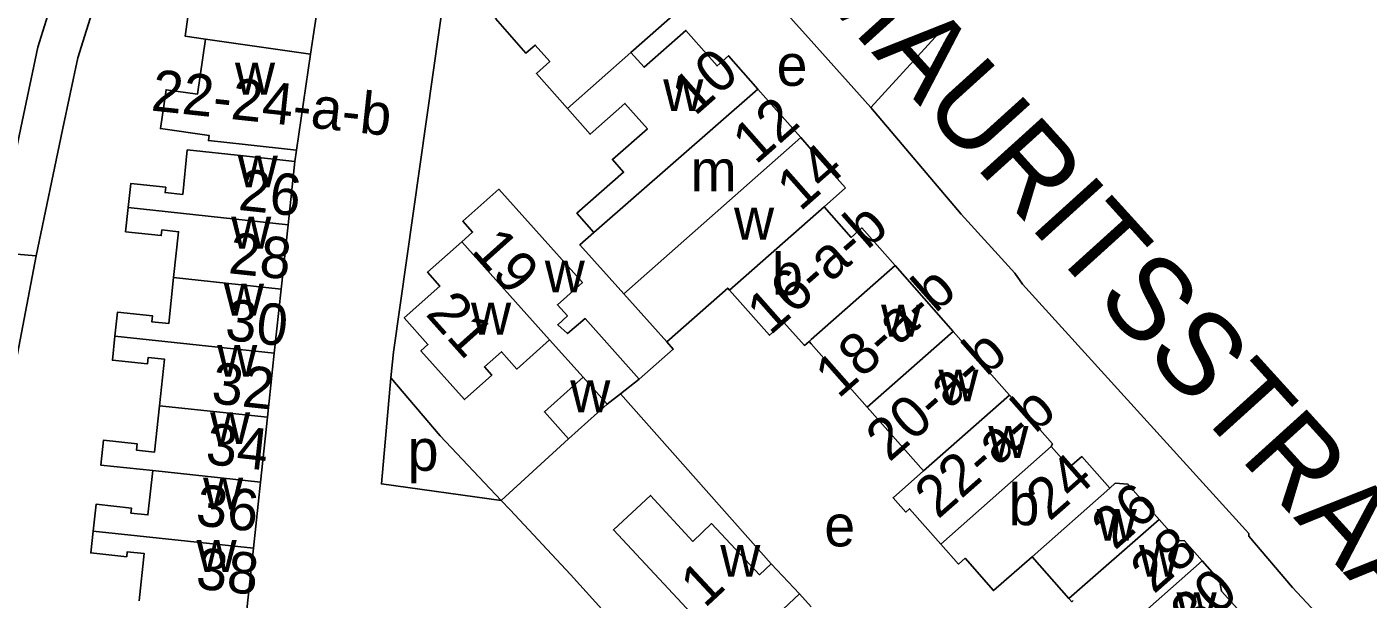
# Model space of a CAD drawing. Extents: x 159261 to 160849, y 382514 to 384534.
# Drawn here: x 160624.3 to 160753.7, y 383032.4 to 383087.7 of the extents above; entities that cross this region are included whole.
import ezdxf

# ---------------------------------------------------------------- set-up
doc = ezdxf.new("R2010")
doc.units = 0
for name, color, linetype in [('BLT_Basislijn', 7, 'Continuous'), ('BLT_Bebouwing', 7, 'Continuous'), ('BLT_Centroide', 7, 'Continuous'), ('BLT_Huisnummer', 7, 'Continuous'), ('BLT_Huisnummer_ tussenligend', 7, 'Continuous'), ('BLT_Huisnummer_reeks', 7, 'Continuous'), ('BLT_Onderverdeling_panden', 7, 'Continuous'), ('BLT_Straatnaam_hoofdweg', 7, 'Continuous'), ('BLT_Vlakafsluiter', 7, 'Continuous')]:
    doc.layers.add(name, color=color, linetype=linetype)

msp = doc.modelspace()

# ---------------------------------------------------------------- linework, layer by layer
at = {"layer": 'BLT_Basislijn'}
for p, q in [((160650.36, 383075.76), (160650.2, 383074.67)), ((160621.23, 383065.87), (160625.25, 383065.55)), ((160696.14, 383035.81), (160681.61, 383052.23)), ((160676.59, 383047.88), (160670.1, 383041.92))]:
    msp.add_line(p, q, dxfattribs=at)
for points in [[(160682.18, 383106.36), (160683.55, 383105.24), (160684.96, 383103.12), (160700, 383086.31)], [(160621.23, 383065.87), (160623.87, 383078.53), (160625.39, 383085.68), (160627.98, 383093.98), (160629.41, 383098.07)], [(160625.25, 383065.55), (160627.78, 383077.71), (160629.27, 383084.67), (160631.78, 383092.72), (160633.52, 383097.7)], [(160664.78, 383092.12), (160659.72, 383056.26), (160659.44, 383053.76)], [(160700, 383086.31), (160705.76, 383079.87)], [(160705.76, 383079.87), (160714.48, 383069.58), (160719.65, 383063.88), (160720.38, 383062.82), (160742.22, 383038.75), (160742.22, 383038.49), (160746.42, 383033.51), (160772.56, 383005.52)], [(160618.36, 383042.52), (160620.8, 383042.42), (160625.25, 383065.55)], [(160686.09, 383057.24), (160686.69, 383056.53), (160683.41, 383053.65)], [(160659.44, 383053.76), (160658.55, 383043.53), (160670.1, 383041.92)], [(160659.44, 383053.76), (160664.22, 383048.17), (160670.1, 383041.92)], [(160700, 383009.05), (160676.77, 383034.77), (160670.95, 383041.01), (160670.1, 383041.92)]]:
    msp.add_lwpolyline(points, dxfattribs=at)
at = {"layer": 'BLT_Bebouwing'}
for p, q in [((160652.55, 383090.74), (160651.71, 383085.03)), ((160650.36, 383075.76), (160651.71, 383085.03)), ((160699, 383076.96), (160694.87, 383081.65)), ((160700, 383075.83), (160699, 383076.96)), ((160703.3, 383072.1), (160700, 383075.83)), ((160649.55, 383068.55), (160650.2, 383074.67)), ((160701.25, 383070.29), (160703.3, 383072.1)), ((160648.88, 383062.33), (160649.55, 383068.55)), ((160648.21, 383056.14), (160648.88, 383062.33)), ((160686.09, 383057.24), (160681.92, 383061.88)), ((160678.01, 383053.83), (160674.77, 383057.44)), ((160700, 383057.06), (160699.8, 383057.29)), ((160647.55, 383049.96), (160648.21, 383056.14)), ((160683.41, 383053.65), (160681.61, 383052.23)), ((160646.88, 383043.7), (160647.55, 383049.96)), ((160646.2, 383037.31), (160646.88, 383043.7)), ((160645.53, 383031.12), (160646.2, 383037.31)), ((160696.14, 383035.81), (160698.86, 383032.9)), ((160698.86, 383032.9), (160700, 383031.67))]:
    msp.add_line(p, q, dxfattribs=at)
for points in [[(160676.48, 383079.78), (160673.49, 383083.16), (160674.78, 383084.3), (160673.38, 383085.89), (160672.49, 383085.11), (160669.54, 383088.46), (160680.54, 383098.16), (160683.77, 383094.51), (160682.44, 383093.34), (160683.46, 383092.18), (160683.79, 383092.47), (160683.95, 383092.28), (160685.48, 383092.18), (160686.92, 383090.55), (160686.87, 383088.95), (160682.61, 383085.19)], [(160642.06, 383092.27), (160641.72, 383089.97), (160640.1, 383090.21), (160639.6, 383086.77), (160641.57, 383086.48)], [(160694.87, 383081.65), (160692.03, 383084.86), (160690.93, 383083.89), (160687.91, 383087.31), (160683.88, 383083.75), (160682.61, 383085.19)], [(160641.57, 383086.48), (160640.79, 383081.15), (160637.77, 383081.59), (160637.23, 383077.84), (160641.93, 383077.16), (160641.86, 383076.67), (160645.39, 383076.29), (160650.36, 383075.76)], [(160679.05, 383067.8), (160677.41, 383069.66), (160681.91, 383073.62), (160680.83, 383074.85), (160684.2, 383077.82), (160682.04, 383080.26), (160678.67, 383077.29), (160676.48, 383079.78)], [(160634.11, 383070.2), (160634.36, 383072.53), (160637.73, 383072.17), (160637.68, 383071.65), (160639.37, 383071.47), (160639.8, 383075.78)], [(160650.2, 383074.67), (160645.23, 383075.2), (160639.8, 383075.78)], [(160683.41, 383053.65), (160678.2, 383059.49), (160676.5, 383058.04), (160675.56, 383058.9), (160676.49, 383059.74), (160675.52, 383060.82), (160677.93, 383062.97), (160673.2, 383068.25), (160669.87, 383071.97), (160666.41, 383068.88), (160667.34, 383067.84), (160666.29, 383066.9)], [(160638.49, 383063.44), (160638.97, 383067.88), (160637.36, 383068.05), (160637.3, 383067.5), (160633.86, 383067.87), (160634.11, 383070.2)], [(160708.09, 383064.6), (160704.89, 383068.24), (160703.86, 383067.33), (160701.25, 383070.29)], [(160681.92, 383061.88), (160677.68, 383066.6), (160679.05, 383067.8)], [(160666.29, 383066.9), (160663, 383063.96), (160664.19, 383062.63), (160660.74, 383059.55), (160663.03, 383056.99), (160662.35, 383056.38), (160666.57, 383051.67), (160669.19, 383054.02), (160668.48, 383054.82), (160670.12, 383056.29), (160671.62, 383054.61), (160674.77, 383057.44)], [(160713.71, 383058.24), (160708.09, 383064.6)], [(160632.84, 383057.79), (160633.09, 383060.11), (160636.46, 383059.74), (160636.4, 383059.17), (160638.02, 383059), (160638.49, 383063.44)], [(160692.13, 383062.24), (160691.96, 383062.43), (160686.09, 383057.24)], [(160699.8, 383057.29), (160699.35, 383056.89), (160697.37, 383059.12), (160695.97, 383057.88), (160692.13, 383062.24)], [(160719.13, 383052.09), (160713.71, 383058.24)], [(160637.14, 383051.07), (160637.62, 383055.56), (160636.04, 383055.73), (160635.97, 383055.11), (160632.6, 383055.47), (160632.84, 383057.79)], [(160705.41, 383050.93), (160700, 383057.06)], [(160678.01, 383053.83), (160674.27, 383050.47), (160676.59, 383047.88)], [(160680.31, 383051.22), (160681.61, 383052.23)], [(160723.15, 383047.14), (160723.28, 383047.39), (160719.13, 383052.09)], [(160636.48, 383044.81), (160631.47, 383045.35), (160631.73, 383047.74), (160634.99, 383047.39), (160634.93, 383046.78), (160636.66, 383046.59), (160637.14, 383051.07)], [(160676.59, 383047.88), (160680.31, 383051.22)], [(160710.84, 383044.78), (160705.41, 383050.93)], [(160728.81, 383043.12), (160726.11, 383046.17), (160724.93, 383045.13), (160723.15, 383047.14)], [(160630.73, 383038.97), (160631.01, 383041.56), (160634.43, 383041.19), (160634.37, 383040.71), (160636.02, 383040.53), (160636.48, 383044.81)], [(160712.51, 383037.7), (160709.49, 383041.12), (160709.14, 383040.81), (160707.91, 383042.19), (160710.84, 383044.78)], [(160733.58, 383040.1), (160730.56, 383043.51), (160729.34, 383043.59), (160728.81, 383043.12)], [(160696.14, 383035.81), (160695.01, 383034.75), (160690.4, 383039.69), (160688.57, 383037.98), (160684.49, 383042.41), (160680.92, 383039.09), (160689.73, 383029.64), (160689.57, 383029.5), (160692.22, 383026.7)], [(160737.72, 383036.1), (160736.02, 383038.03), (160735.37, 383038.07), (160733.58, 383040.1)], [(160635.16, 383032.23), (160635.66, 383036.8), (160634.02, 383036.98), (160633.97, 383036.49), (160630.5, 383036.86), (160630.73, 383038.97)], [(160721.31, 383036.49), (160717.58, 383033.22), (160714.84, 383036.34), (160714.2, 383035.78), (160712.51, 383037.7)], [(160724.86, 383032.47), (160721.31, 383036.49)], [(160741.13, 383031.45), (160739.6, 383033.18), (160739.39, 383034.21), (160737.72, 383036.1)], [(160725.27, 383032.26), (160725.14, 383032.15), (160724.86, 383032.47)]]:
    msp.add_lwpolyline(points, dxfattribs=at)
at = {"layer": 'BLT_Onderverdeling_panden'}
for p, q in [((160641.57, 383086.48), (160651.71, 383085.03)), ((160682.61, 383085.19), (160676.48, 383079.78)), ((160679.05, 383067.8), (160694.87, 383081.65)), ((160681.92, 383061.88), (160699, 383076.96)), ((160634.11, 383070.2), (160649.55, 383068.55)), ((160692.13, 383062.24), (160701.25, 383070.29)), ((160666.29, 383066.9), (160674.77, 383057.44)), ((160700, 383057.46), (160708.09, 383064.6)), ((160638.49, 383063.44), (160648.88, 383062.33)), ((160705.41, 383050.93), (160713.71, 383058.24)), ((160632.84, 383057.79), (160648.21, 383056.14)), ((160699.8, 383057.29), (160700, 383057.46)), ((160678.01, 383053.83), (160680.31, 383051.22)), ((160710.84, 383044.78), (160719.13, 383052.09)), ((160637.14, 383051.07), (160647.55, 383049.96)), ((160712.51, 383037.7), (160723.15, 383047.14)), ((160636.48, 383044.81), (160646.88, 383043.7)), ((160721.31, 383036.49), (160728.81, 383043.12)), ((160724.86, 383032.47), (160733.58, 383040.1)), ((160630.73, 383038.97), (160646.2, 383037.31)), ((160729.74, 383029.05), (160737.72, 383036.1)), ((160698.86, 383032.9), (160692.22, 383026.7))]:
    msp.add_line(p, q, dxfattribs=at)
at = {"layer": 'BLT_Vlakafsluiter'}
msp.add_line((160712.68, 383087.43), (160705.76, 383079.87), dxfattribs=at)

# ---------------------------------------------------------------- texts
at = {"layer": 'BLT_Centroide'}
for s, p in [('w', (160644.42, 383081.12)), ('e', (160696.67, 383081.96)), ('w', (160685.73, 383079.52)), ('w', (160644.69, 383072.16)), ('m', (160688.37, 383071.78)), ('w', (160692.56, 383067.12)), ('w', (160644.05, 383066.25)), ('b', (160696.23, 383061.79)), ('w', (160674.3, 383062.02)), ('w', (160643.35, 383059.78)), ('w', (160667.19, 383057.94)), ('w', (160706.75, 383057.75)), ('w', (160642.7, 383053.88)), ('w', (160712.27, 383051.5)), ('w', (160676.76, 383050.45)), ('w', (160642.02, 383047.38)), ('w', (160717.09, 383046.03)), ('p', (160661.08, 383044.79)), ('w', (160641.34, 383041.06)), ('b', (160719.05, 383039.54)), ('e', (160701.27, 383037.49)), ('w', (160727.55, 383038.03)), ('w', (160640.71, 383035.03)), ('w', (160691.23, 383034.56)), ('w', (160731.63, 383034.56)), ('w', (160735.25, 383029.97))]:
    msp.add_text(s, height=4, dxfattribs=at).set_placement(p)
at = {"layer": 'BLT_Huisnummer'}
for s, rotation, p in [('10', 41.4468, (160688.78, 383078.96)), ('14', 41.4223, (160698.93, 383069.76)), ('26', 353.8848, (160644.65, 383069.99)), ('19', 311.8346, (160667.1, 383065.99)), ('30', 353.8827, (160643.37, 383057.44)), ('21', 311.839, (160662.71, 383059.89)), ('34', 353.8882, (160641.49, 383045.46)), ('24', 41.4226, (160722.99, 383039.84)), ('26', 41.4222, (160729.29, 383037.04)), ('1', 42.9922, (160689.72, 383031.45)), ('30', 41.418, (160736.92, 383028.77))]:
    msp.add_text(s, height=4, rotation=rotation, dxfattribs=at).set_placement(p)
at = {"layer": 'BLT_Huisnummer_ tussenligend'}
for s, rotation, p in [('12', 41.4269, (160694.65, 383074.27)), ('28', 353.8848, (160643.7, 383063.88)), ('32', 353.8827, (160642.05, 383051.33)), ('36', 353.8882, (160640.54, 383039.54)), ('28', 41.4222, (160733.05, 383032.82)), ('38', 353.8882, (160640.55, 383033.43))]:
    msp.add_text(s, height=4, rotation=rotation, dxfattribs=at).set_placement(p)
at = {"layer": 'BLT_Huisnummer_reeks'}
for s, rotation, p in [('22-24-a-b', 353.8848, (160636.24, 383079.59)), ('16-a-b', 41.4223, (160696.05, 383057.8)), ('18-a-b', 41.4184, (160702.62, 383051.68)), ('20-a-b', 41.4224, (160707.53, 383045.56)), ('22-a-b', 41.4224, (160712.23, 383040.05))]:
    msp.add_text(s, height=4, rotation=rotation, dxfattribs=at).set_placement(p)
at = {"layer": 'BLT_Straatnaam_hoofdweg'}
msp.add_text('MAURITSSTRAAT', height=8, rotation=312.175, dxfattribs=at).set_placement((160699.78, 383091.8))

doc.saveas('drawing.dxf')
